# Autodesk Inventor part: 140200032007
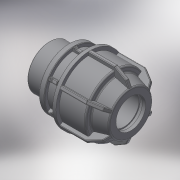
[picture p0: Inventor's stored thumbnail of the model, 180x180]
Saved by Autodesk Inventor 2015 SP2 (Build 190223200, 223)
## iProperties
Created: 2017-08
Part Number: 140200032007
Material: Generic
Description: PLASSON L. 14 MALE ADAPTOR (SILVER) 32-3/4''
Document SubType Name: Modeling
Designer: KIM
Density: 1 g/cm^3
Appearance: Default
Author: KIM
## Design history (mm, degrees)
derived "140200.ipt"
feature "Solid1::140200.ipt"
tag "TaggingFeature1"
body "Solid1"
other parameters: "d1" = 32, "d4" = 15 deg, "d5" = 39.6, "d6" = 13.068, "d10" = 61, "d16" = 32.64, "d17" = 3, "d18" = 82, "d19" = 6, "d21" = 6, "d22" = 35.69535, "d24" = 3, "d25" = 54.9, "d26" = 45.75, "d27" = 3, "d28" = 135 deg, "d29" = 1.8, "d31" = 1.6, "d44" = 0.64, "d45" = 0.96, "d46" = 150 deg, "d49" = 3.05, "d50" = 0, "d51" = 1.83, "d52" = 1.22, "d53" = 45 deg, "d54" = 21, "d55" = 8.4, "d56" = 3.05, "d57" = 0, "d58" = 0.96, "d59" = 0.64, "d61" = 360 deg, "d63" = 26.441, "d64" = 19.2, "d66" = 39.6615, "d_" = 32, "R_" = 26.441, "E_" = 61, "H_" = 82
